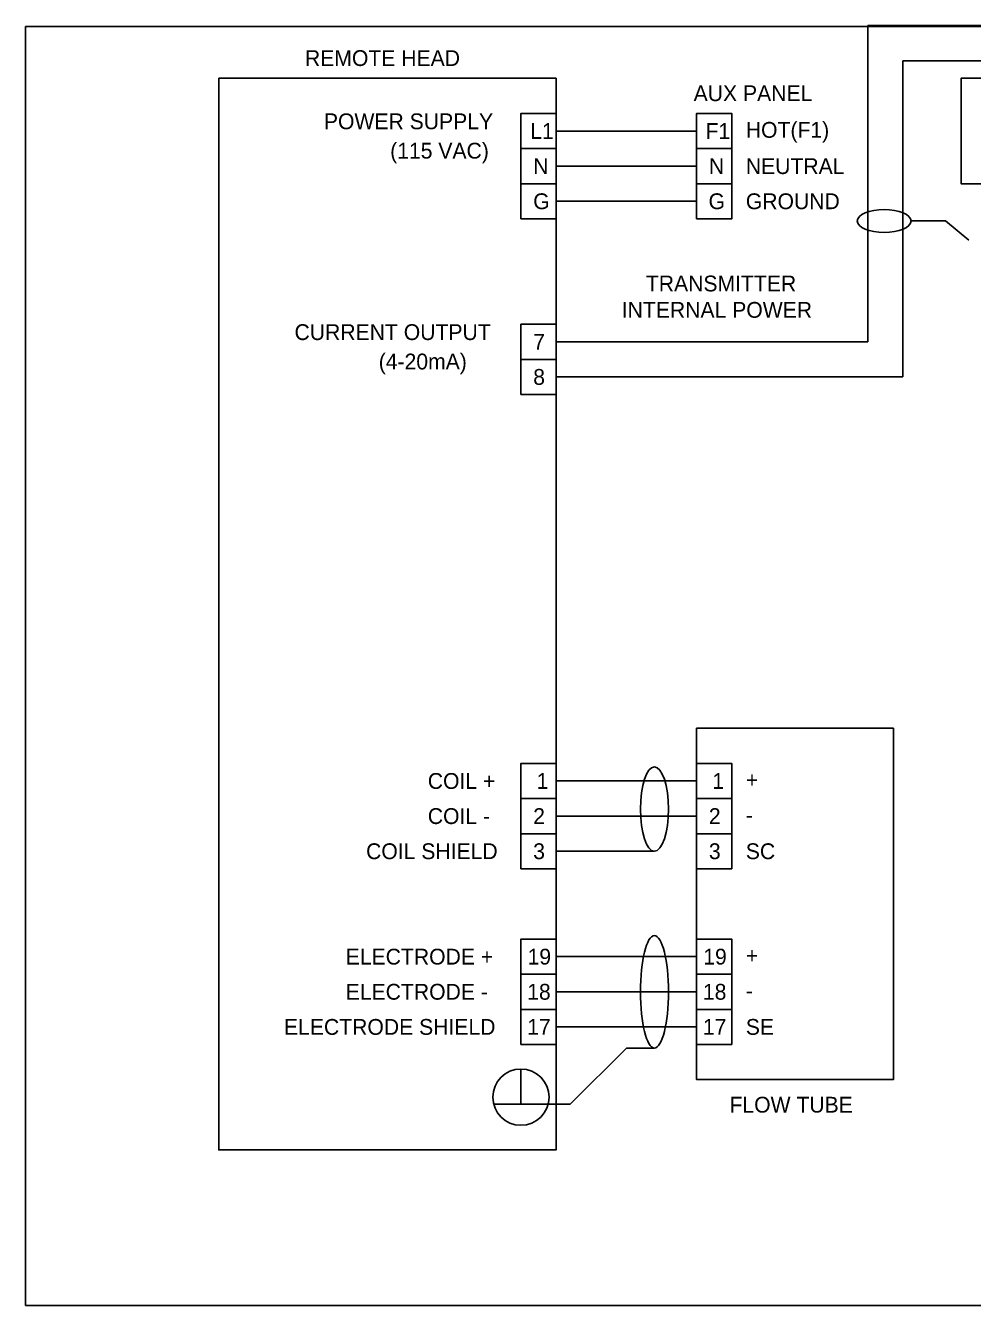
# Model space of a CAD drawing. Extents: x 10010.3 to 10109.1, y 10088 to 10139.5.
# Drawn here: x 10010.27 to 10043.95, y 10093.97 to 10139.5 of the extents above; entities that cross this region are included whole.
import ezdxf

# ---------------------------------------------------------------- set-up
doc = ezdxf.new("R2010")
doc.units = 0
for name, color, linetype in [('Default', 7, 'Continuous'), ('G-DETL-GRID', 7, 'Continuous'), ('G-DETL-LINE', 7, 'Continuous')]:
    doc.layers.add(name, color=color, linetype=linetype)

msp = doc.modelspace()

# ---------------------------------------------------------------- linework, layer by layer
at = {"layer": 'Default'}
for p, q in [((10029.136, 10135.75), (10034.136, 10135.75)), ((10029.136, 10134.5), (10034.136, 10134.5)), ((10029.136, 10133.25), (10034.136, 10133.25)), ((10029.136, 10112.625), (10034.136, 10112.625)), ((10029.136, 10111.375), (10034.136, 10111.375)), ((10029.136, 10110.125), (10032.636, 10110.125)), ((10029.136, 10106.375), (10034.136, 10106.375)), ((10029.136, 10105.125), (10034.136, 10105.125)), ((10029.136, 10103.875), (10034.136, 10103.875)), ((10031.636, 10103.125), (10029.636, 10101.125)), ((10032.636, 10103.125), (10031.636, 10103.125)), ((10027.886, 10101.125), (10027.886, 10102.375)), ((10028.854, 10101.125), (10026.917, 10101.125)), ((10028.854, 10101.125), (10029.636, 10101.125))]:
    msp.add_line(p, q, dxfattribs=at)
for points in [[(10017.136, 10137.625), (10029.136, 10137.625), (10029.136, 10099.5), (10017.136, 10099.5), (10017.136, 10137.625)], [(10027.886, 10135.125), (10029.136, 10135.125), (10029.136, 10136.375), (10027.886, 10136.375), (10027.886, 10135.125)], [(10034.136, 10135.125), (10035.386, 10135.125), (10035.386, 10136.375), (10034.136, 10136.375), (10034.136, 10135.125)], [(10027.886, 10133.875), (10029.136, 10133.875), (10029.136, 10135.125), (10027.886, 10135.125), (10027.886, 10133.875)], [(10034.136, 10133.875), (10035.386, 10133.875), (10035.386, 10135.125), (10034.136, 10135.125), (10034.136, 10133.875)], [(10027.886, 10132.625), (10029.136, 10132.625), (10029.136, 10133.875), (10027.886, 10133.875), (10027.886, 10132.625)], [(10034.136, 10132.625), (10035.386, 10132.625), (10035.386, 10133.875), (10034.136, 10133.875), (10034.136, 10132.625)], [(10027.886, 10127.625), (10029.136, 10127.625), (10029.136, 10128.875), (10027.886, 10128.875), (10027.886, 10127.625)], [(10027.886, 10126.375), (10029.136, 10126.375), (10029.136, 10127.625), (10027.886, 10127.625), (10027.886, 10126.375)], [(10034.136, 10114.5), (10041.136, 10114.5), (10041.136, 10102), (10034.136, 10102), (10034.136, 10114.5)], [(10027.886, 10112), (10029.136, 10112), (10029.136, 10113.25), (10027.886, 10113.25), (10027.886, 10112)], [(10034.136, 10112), (10035.386, 10112), (10035.386, 10113.25), (10034.136, 10113.25), (10034.136, 10112)], [(10027.886, 10110.75), (10029.136, 10110.75), (10029.136, 10112), (10027.886, 10112), (10027.886, 10110.75)], [(10034.136, 10110.75), (10035.386, 10110.75), (10035.386, 10112), (10034.136, 10112), (10034.136, 10110.75)], [(10027.886, 10109.5), (10029.136, 10109.5), (10029.136, 10110.75), (10027.886, 10110.75), (10027.886, 10109.5)], [(10034.136, 10109.5), (10035.386, 10109.5), (10035.386, 10110.75), (10034.136, 10110.75), (10034.136, 10109.5)], [(10027.886, 10105.75), (10029.136, 10105.75), (10029.136, 10107), (10027.886, 10107), (10027.886, 10105.75)], [(10034.136, 10105.75), (10035.386, 10105.75), (10035.386, 10107), (10034.136, 10107), (10034.136, 10105.75)], [(10027.886, 10104.5), (10029.136, 10104.5), (10029.136, 10105.75), (10027.886, 10105.75), (10027.886, 10104.5)], [(10034.136, 10104.5), (10035.386, 10104.5), (10035.386, 10105.75), (10034.136, 10105.75), (10034.136, 10104.5)], [(10027.886, 10103.25), (10029.136, 10103.25), (10029.136, 10104.5), (10027.886, 10104.5), (10027.886, 10103.25)], [(10034.136, 10103.25), (10035.386, 10103.25), (10035.386, 10104.5), (10034.136, 10104.5), (10034.136, 10103.25)]]:
    msp.add_lwpolyline(points, dxfattribs=at)
msp.add_circle((10027.886, 10101.375), 1, dxfattribs=at)
for centre, major_axis, ratio in [((10032.636, 10111.625), (0, -1.5), 0.333333), ((10032.636, 10105.125), (0, -2), 0.25)]:
    msp.add_ellipse(centre, major_axis=major_axis, ratio=ratio, dxfattribs=at)
at = {"layer": 'G-DETL-GRID'}
msp.add_lwpolyline([(10010.265, 10139.467), (10059.407, 10139.467), (10059.407, 10093.967), (10010.265, 10093.967)], close=True, dxfattribs=at)
at = {"layer": 'G-DETL-LINE'}
for p, q in [((10066.351, 10139.5), (10040.222, 10139.5)), ((10040.222, 10128.25), (10040.222, 10139.5)), ((10041.472, 10127), (10041.472, 10138.25)), ((10062.445, 10138.25), (10041.472, 10138.25)), ((10041.764, 10132.549), (10042.984, 10132.549)), ((10042.984, 10132.549), (10043.817, 10131.87)), ((10040.222, 10128.25), (10029.136, 10128.25)), ((10029.136, 10127), (10041.472, 10127))]:
    msp.add_line(p, q, dxfattribs=at)
msp.add_lwpolyline([(10047.544, 10137.625), (10043.544, 10137.625), (10043.544, 10133.875), (10047.544, 10133.875), (10047.544, 10137.625)], dxfattribs=at)
msp.add_ellipse((10040.807, 10132.549), major_axis=(-0.957, 0), ratio=0.422719, dxfattribs=at)

# ---------------------------------------------------------------- texts
at = {"layer": 'Default'}
for s, height, p in [('REMOTE HEAD', 0.5625, (10020.203, 10138.063)), ('AUX PANEL', 0.5625, (10034.03, 10136.813)), ('POWER SUPPLY', 0.5625, (10020.877, 10135.813)), ('L1', 0.5625, (10028.216, 10135.469)), ('F1', 0.5625, (10034.453, 10135.469)), ('HOT(F1)', 0.5625, (10035.886, 10135.509)), ('(115 VAC)', 0.5625, (10023.234, 10134.768)), ('N', 0.563, (10028.323, 10134.219)), ('N', 0.563, (10034.573, 10134.219)), ('NEUTRAL', 0.5625, (10035.886, 10134.219)), ('G', 0.563, (10028.323, 10132.969)), ('G', 0.563, (10034.56, 10132.969)), ('GROUND', 0.5625, (10035.886, 10132.969)), ('TRANSMITTER', 0.5625, (10032.33, 10130.043)), ('INTERNAL POWER', 0.5625, (10031.473, 10129.105)), ('CURRENT OUTPUT', 0.5625, (10019.832, 10128.313)), ('7', 0.563, (10028.323, 10127.969)), (' (4-20mA)', 0.5625, (10022.618, 10127.268)), ('8', 0.563, (10028.323, 10126.719)), ('COIL +', 0.5625, (10024.573, 10112.344)), ('1', 0.563, (10028.444, 10112.344)), ('1', 0.563, (10034.694, 10112.344)), ('+', 0.563, (10035.886, 10112.384)), ('COIL -', 0.5625, (10024.573, 10111.094)), ('2', 0.563, (10028.323, 10111.094)), ('2', 0.563, (10034.573, 10111.094)), ('-', 0.563, (10035.886, 10111.134)), ('COIL SHIELD', 0.5625, (10022.377, 10109.844)), ('3', 0.563, (10028.323, 10109.844)), ('3', 0.563, (10034.573, 10109.844)), ('SC', 0.5625, (10035.886, 10109.844)), ('ELECTRODE +', 0.5625, (10021.653, 10106.094)), ('19', 0.5625, (10028.122, 10106.094)), ('19', 0.5625, (10034.372, 10106.094)), ('+', 0.563, (10035.886, 10106.134)), ('ELECTRODE -', 0.5625, (10021.653, 10104.844)), ('18', 0.5625, (10028.109, 10104.844)), ('18', 0.5625, (10034.359, 10104.844)), ('-', 0.563, (10035.886, 10104.884)), ('ELECTRODE SHIELD', 0.5625, (10019.457, 10103.594)), ('17', 0.5625, (10028.109, 10103.594)), ('17', 0.5625, (10034.359, 10103.594)), ('SE', 0.5625, (10035.886, 10103.594)), ('FLOW TUBE', 0.5625, (10035.305, 10100.827))]:
    msp.add_text(s, height=height, dxfattribs=at).set_placement(p)

doc.saveas('drawing.dxf')
